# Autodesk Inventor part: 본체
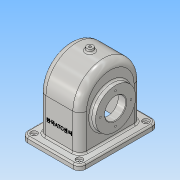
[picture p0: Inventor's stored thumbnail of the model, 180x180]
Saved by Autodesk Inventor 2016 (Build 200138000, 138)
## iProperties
Created: 2018-08
Part Number: 본체
Material: 알루미늄 6061
Document SubType Name: Modeling
Designer: Administrator
Density: 2.7 g/cm^3
Appearance: 알루미늄 - 평지
Mass: 1091.9 g
Surface Area: 1182.65 cm^2
Volume: 404.407 cm^3
Author: Administrator
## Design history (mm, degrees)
sketch "스케치1"
  geometry: L1 (-55, -75)-(55, -75); L2 (55, -75)-(55, 75); L3 (55, 75)-(-55, 75); L4 (-55, 75)-(-55, -75); L5 (-55, -75)-(55, 75); L6 (55, -75)-(-55, 75); 1 further point
  constraints: 12 end point, 2 midpoint, 2 parallel, 1 horizontal, 1 perpendicular
  dimensions: "d0" = 110 distance of L3.end L2.end; "d1" = 150 distance of L2.end L1.end
extrude "돌출1" new body sketch "스케치1" distance "d2" = 10; taper "d3" = 0 deg
sketch "스케치2"
  geometry: L1 (75, 10)-(-75, 10) reference; L2 (-58, 10)-(58, 10); L3 (58, 10)-(58, 78); L4 (58, 78)-(-58, 78); L5 (-58, 78)-(-58, 10); L6 (75, 0)-(-75, 0) reference; A1 r 58 centre (0, 78) between (58, 78) and (-58, 78); 2 further points
  constraints: 8 end point, 2 midpoint, 2 parallel, 2 point on circle, 1 centre point, 1 horizontal, 1 perpendicular, 1 point on line, 1 vertical alignment
  dimensions: "d4" = 78 distance between parallel lines of L6 L4; "d5" = 58 radius of A1
extrude "돌출2" join sketch "스케치2" stored distance "d6" = 77; taper "d7" = 0 deg
feature "쉘1" dims "d8" = 23, "d9" = 21.5, "d10" = 5, "d113" = 6
sketch "스케치3"
  geometry: L1 (58.727, 65)-(-57.25, 65); L2 (-33.5, 0)-(33.5, 0) reference; L3 (38.5, 78)-(38.5, 136) reference; L4 (-38.5, 136)-(-38.5, 78) reference; L5 (-38.5, 103)-(-48.5, 103); L6 (-48.5, 103)-(-48.5, 65); L7 (-38.5, 103)-(-38.5, 65); L8 (33.5, 78)-(33.5, 130) reference; L9 (43.5, 65)-(43.5, 103); L10 (33.5, 104.747)-(19.5, 93); L11 (19.5, 93)-(19.5, 65); L12 (43.5, 103)-(38.5, 103); L13 (38.5, 103)-(38.5, 65); L14 (38.5, 78)-(38.5, 10) reference; L15 (33.5, 104.747)-(33.5, 65); 1 further point
  constraints: 20 end point, 12 point on line, 4 perpendicular, 1 horizontal, 1 vertical
  dimensions: "d11" = 65 distance between parallel lines of L2 L1; "d17" = 76 diameter of L5 L1; "d18" = 87 distance between parallel lines of L6 L3; "d121" = 50 deg angle of L11 L10; "d122" = 24 distance between parallel lines of L11 L9; "d124" = 56 diameter of L10.end L1; "d125" = 76 diameter of L12 L1; "d126" = 5 distance between parallel lines of L3 L9
revolve "회전1" sketch "스케치3" stored, may be unused: angle "d19" = 90 deg
hole "구멍1" diameter "d22" = 40; stored, may be unused: countersink angle "d26" = 90 deg, drill point angle "d28" = 118 deg; dims "d20" = 10, "d21" = 10, "d23" = 6, "d24" = 4, "d25" = 2, "d27" = 8
node "작업 평면1"
sketch "스케치4"
  geometry: C1 r 6 at (0, 0); 1 further point
  constraints: 1 centre point, 1 coincident
  dimensions: "d30" = 12 diameter of C1
extrude "돌출3" join sketch "스케치4" stored distance "d31" = 77; taper "d32" = 5 deg
hole "구멍2" diameter "d35" = 4.459; stored, may be unused: countersink angle "d39" = 90 deg, drill point angle "d41" = 118 deg; dims "d36" = 10, "d37" = 4, "d38" = 2, "d40" = 12.8, "d111" = 10, "d112" = 10
fillet "모깎기1" dims "d42" = 12
hole "구멍3" diameter "d45" = 5; stored, may be unused: countersink angle "d49" = 90 deg, drill point angle "d51" = 118 deg; dims "d43" = 10, "d44" = 10, "d46" = 10, "d47" = 12, "d48" = 4, "d50" = 12.8
hole "구멍4" diameter "d54" = 5; stored, may be unused: countersink angle "d58" = 90 deg, drill point angle "d60" = 118 deg; dims "d52" = 10, "d53" = 10, "d55" = 10, "d56" = 12, "d57" = 4, "d59" = 12.8
hole "구멍5" diameter "d63" = 5; stored, may be unused: countersink angle "d67" = 90 deg, drill point angle "d69" = 118 deg; dims "d61" = 10, "d62" = 10, "d64" = 10, "d65" = 12, "d66" = 4, "d68" = 12.8
hole "구멍6" diameter "d72" = 5; stored, may be unused: countersink angle "d76" = 90 deg, drill point angle "d78" = 118 deg; dims "d70" = 10, "d71" = 10, "d73" = 10, "d74" = 12, "d75" = 4, "d77" = 12.8
sketch "스케치6" dims "d90" = 58
  geometry: C1 r 38 at (0, 0) reference; 3 further points
  constraints: 2 horizontal alignment, 3 other
hole "구멍8" sketch "스케치6" at (-29, 0) diameter "d91" = 3.242; stored, may be unused: countersink angle "d95" = 90 deg, drill point angle "d97" = 118 deg; dims "d92" = 8, "d93" = 12, "d94" = 4, "d96" = 10
fillet "모깎기2" dims "d101" = 13
fillet "모깎기3" dims "d102" = 8
fillet "모깎기4" dims "d103" = 3
chamfer "모따기1" distance "d104" = 1; stored, may be unused: second distance "d105" = 2, angle "d106" = 45 deg
sketch "스케치7"
  geometry: L1 (-13, 0)-(-13, -65) reference; L2 (-17.5, -78)-(68.5, -78) reference; 2 further points
  constraints: 1 other
  dimensions: "d107" = 38.5 distance from line of point (25.5, -38) L1; "d108" = 40 distance from line of L2 point (25.5, -38)
feature "엠보싱1" sketch "스케치7" dims "d0" = 110, "d1" = 150, "d109" = 0.5, "d110" = 0
sketch "스케치8" dims "d127" = 58
  geometry: C1 r 38 at (0, 0) reference; 3 further points
  constraints: 2 horizontal alignment, 3 other
hole "구멍9" sketch "스케치8" at (29, 0) diameter "d128" = 3.242; stored, may be unused: countersink angle "d132" = 90 deg, drill point angle "d134" = 118 deg; dims "d129" = 8, "d130" = 12, "d131" = 4, "d133" = 10
fillet "모깎기6" dims "d138" = 3
chamfer "모따기2" distance "d139" = 1; stored, may be unused: second distance "d140" = 2, angle "d141" = 45 deg
node "솔리드1"
pattern_circular "원형 패턴2" dims angle "d99" = 360 deg
pattern_circular "원형 패턴3" dims angle "d136" = 360 deg
other parameters: "d29" = 142
